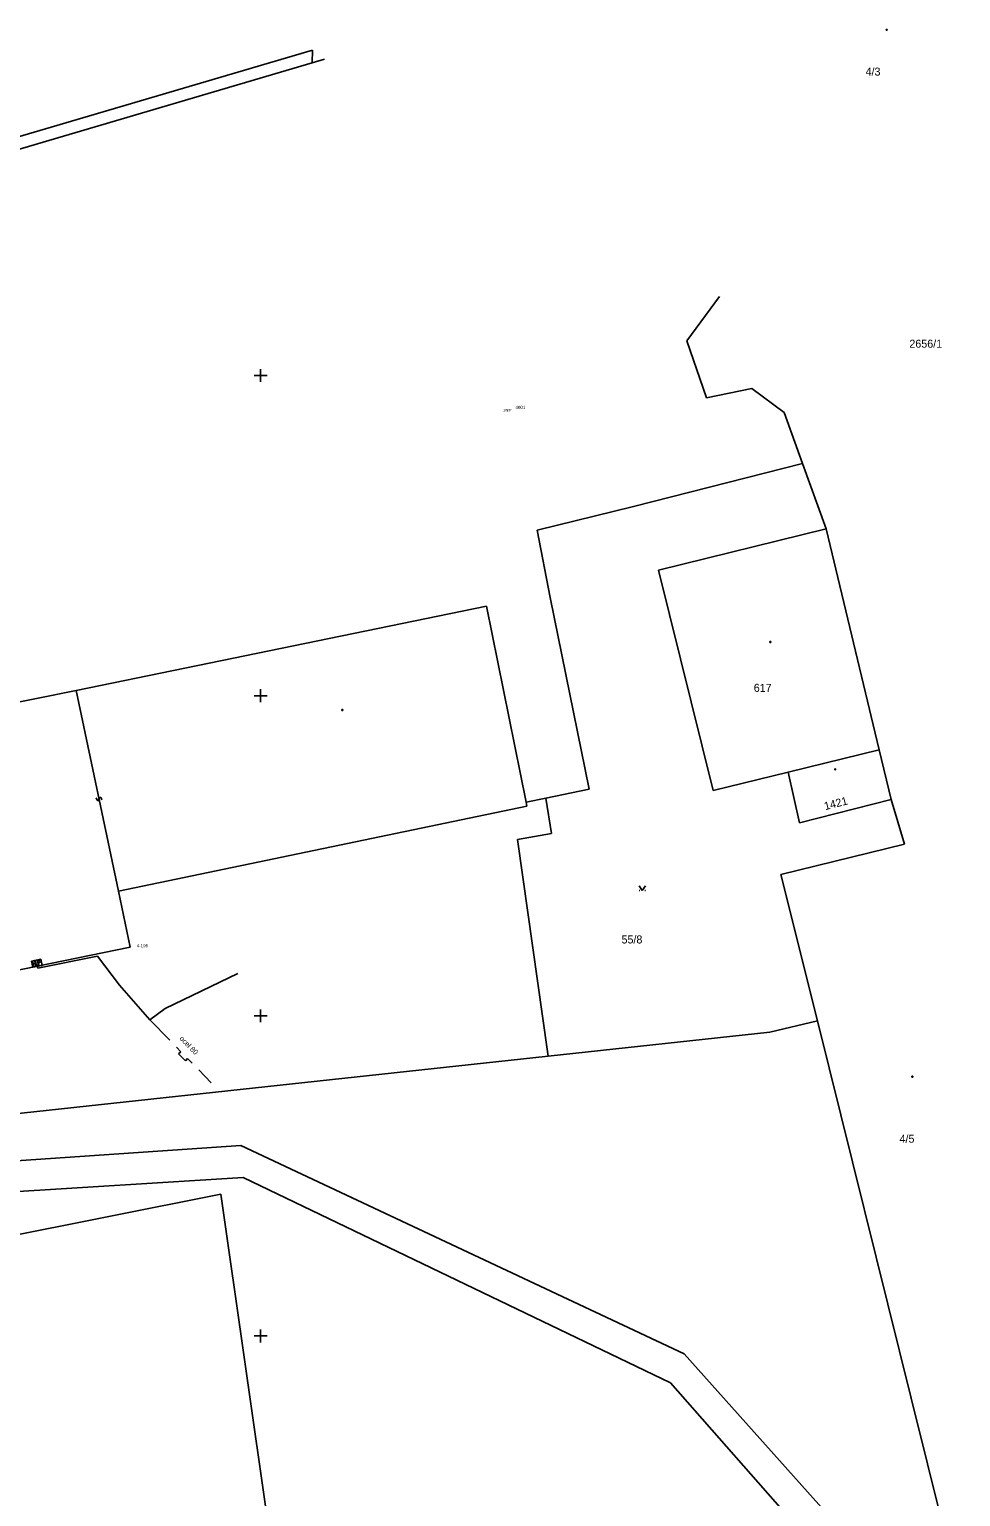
# Model space of a CAD drawing. Extents: x -651478 to -651308, y -994378 to -994071.
# Drawn here: x -651374.4 to -651316.3, y -994310 to -994218.4 of the extents above; entities that cross this region are included whole.
import ezdxf

# ---------------------------------------------------------------- set-up
doc = ezdxf.new("R2010")
doc.units = 0
for name, color, linetype in [('18_TECKY_BODU', 7, 'Continuous'), ('19_CISLA_BODU', 7, 'Continuous'), ('20_REDUKOVANE_VYSKY_BODU', 7, 'Continuous'), ('36_PLYN-VEDENI', 7, 'Continuous'), ('37_PLYN-OBEKTY', 7, 'Continuous'), ('61_UPLNE_VYSKY_BODU', 7, 'Continuous'), ('_KM', 7, 'Continuous'), ('ROZP', 7, 'Continuous'), ('rybnik oprava', 7, 'Continuous')]:
    doc.layers.add(name, color=color, linetype=linetype)

# ---------------------------------------------------------------- blocks, each defined once
blk = doc.blocks.new('POINT_DISPLAY')
blk.add_line((0, 0), (0, 0))
blk = doc.blocks.new('Z402')
for p, q in [((-0.02, 0.02), (0.04, 0.02)), ((-0.02, -0.04), (-0.02, 0.02)), ((0.04, 0.02), (0.04, -0.04)), ((0.04, -0.04), (-0.02, -0.04))]:
    blk.add_line(p, q)
blk = doc.blocks.new('Z3140')
for p, q in [((-0.2, 0.3), (0, 0)), ((-0.2, 0), (-0.16, 0)), ((0, 0), (0.2, 0.3)), ((0.16, 0), (0.2, 0))]:
    blk.add_line(p, q)
blk = doc.blocks.new('Z218')
for p, q in [((-0.04, 0.14), (-0.08, 0.1)), ((-0.08, 0.1), (-0.08, 0.06)), ((-0.08, 0.06), (-0.04, 0.02)), ((0.1, 0.16), (-0.04, 0.14)), ((-0.04, 0.02), (0.04, -0.02)), ((0.04, -0.14), (-0.1, -0.16)), ((0.04, -0.02), (0.08, -0.06)), ((0.08, -0.1), (0.04, -0.14)), ((0.08, -0.06), (0.08, -0.1))]:
    blk.add_line(p, q)
blk = doc.blocks.new('Z70')
for p, q in [((-0.4, 0), (0.4, 0)), ((0, -0.4), (0, 0.4))]:
    blk.add_line(p, q)
blk = doc.blocks.new('Z632')
for p, q in [((-0.7, 0), (-0.3, 0)), ((-0.3, 0), (-0.3, -0.2)), ((0.3, -0.2), (0.3, 0)), ((0.3, 0), (0.7, 0)), ((-0.3, -0.2), (0.3, -0.2))]:
    blk.add_line(p, q)
blk = doc.blocks.new('Z56')
for p, q in [((-0.3, 0), (-0.3, 0.4)), ((-0.3, 0.4), (0.3, 0.4)), ((0.3, 0), (-0.3, 0)), ((-0.22, 0.34), (-0.22, 0.06)), ((-0.22, 0.2), (-0.1, 0.2)), ((-0.1, 0.06), (-0.1, 0.34)), ((-0.06, 0.34), (-0.06, 0.12)), ((-0.06, 0.12), (-0.04, 0.08)), ((-0.04, 0.08), (-0.02, 0.06)), ((-0.02, 0.06), (0.02, 0.06)), ((0.02, 0.06), (0.04, 0.08)), ((0.04, 0.08), (0.06, 0.12)), ((0.06, 0.12), (0.06, 0.34)), ((0.1, 0.06), (0.1, 0.34)), ((0.1, 0.34), (0.18, 0.34)), ((0.18, 0.2), (0.1, 0.2)), ((0.18, 0.34), (0.22, 0.3)), ((0.22, 0.24), (0.18, 0.2)), ((0.22, 0.3), (0.22, 0.24)), ((0.3, 0.4), (0.3, 0))]:
    blk.add_line(p, q)

msp = doc.modelspace()

# ---------------------------------------------------------------- linework, layer by layer
at = {"layer": '36_PLYN-VEDENI'}
for p, q in [((-651373.924, -994277.023), (-651370.198, -994276.275)), ((-651368.81, -994278.08), (-651370.198, -994276.275)), ((-651373.94, -994276.91), (-651373.924, -994277.023)), ((-651361.42, -994277.35), (-651365.97, -994279.55)), ((-651366.93, -994280.25), (-651368.81, -994278.08)), ((-651365.97, -994279.55), (-651366.93, -994280.25)), ((-651366.93, -994280.25), (-651365.679, -994281.527)), ((-651363.859, -994283.384), (-651363.08, -994284.18))]:
    msp.add_line(p, q, dxfattribs=at)
at = {"layer": '_KM'}
for p, q in [((-651382.1, -994227.92), (-651356.79, -994220.47)), ((-651382.09, -994227.14), (-651356.75, -994219.68)), ((-651356.79, -994220.47), (-651356.75, -994219.68)), ((-651356.79, -994220.47), (-651356.01, -994220.24)), ((-651333.37, -994237.84), (-651331.33, -994235.07)), ((-651333.37, -994237.84), (-651332.14, -994241.4)), ((-651332.14, -994241.4), (-651329.31, -994240.81)), ((-651329.31, -994240.81), (-651327.29, -994242.31)), ((-651326.15, -994245.5), (-651327.29, -994242.31)), ((-651326.15, -994245.5), (-651336.7, -994248.19)), ((-651326.15, -994245.5), (-651324.68, -994249.58)), ((-651336.7, -994248.19), (-651342.72, -994249.66)), ((-651342.72, -994249.66), (-651341.92, -994253.87)), ((-651335.14, -994252.15), (-651324.68, -994249.58)), ((-651324.68, -994249.58), (-651321.37, -994263.38)), ((-651335.14, -994252.15), (-651331.73, -994265.92)), ((-651345.88, -994254.41), (-651371.52, -994259.68)), ((-651343.42, -994266.65), (-651345.88, -994254.41)), ((-651341.92, -994253.87), (-651339.48, -994265.85)), ((-651371.52, -994259.68), (-651384.86, -994262.37)), ((-651371.52, -994259.68), (-651368.87, -994272.22)), ((-651327.05, -994264.77), (-651321.37, -994263.38)), ((-651321.37, -994263.38), (-651320.62, -994266.49)), ((-651331.73, -994265.92), (-651327.05, -994264.77)), ((-651327.05, -994264.77), (-651326.34, -994267.94)), ((-651342.19, -994266.4), (-651339.48, -994265.85)), ((-651368.87, -994272.22), (-651343.37, -994266.9)), ((-651342.19, -994266.4), (-651343.42, -994266.65)), ((-651343.37, -994266.9), (-651343.42, -994266.65)), ((-651342.19, -994266.4), (-651341.83, -994268.62)), ((-651326.34, -994267.94), (-651320.62, -994266.49)), ((-651320.62, -994266.49), (-651319.78, -994269.27)), ((-651341.83, -994268.62), (-651343.95, -994268.98)), ((-651343.95, -994268.98), (-651342.06, -994282.38)), ((-651327.5, -994271.17), (-651319.78, -994269.27)), ((-651325.22, -994280.32), (-651327.5, -994271.17)), ((-651368.14, -994275.72), (-651368.87, -994272.22)), ((-651342.04, -994282.52), (-651328.2, -994281.02)), ((-651328.2, -994281.02), (-651325.22, -994280.32)), ((-651325.22, -994280.32), (-651319.37, -994303.88)), ((-651342.04, -994282.52), (-651388.53, -994287.55)), ((-651342.06, -994282.38), (-651342.04, -994282.52)), ((-651397.46, -994290.57), (-651361.24, -994288.11)), ((-651361.24, -994288.11), (-651333.54, -994301.11)), ((-651396.8, -994292.29), (-651361.1, -994290.11)), ((-651361.1, -994290.11), (-651334.39, -994302.92)), ((-651394.77, -994297.58), (-651362.49, -994291.14)), ((-651362.49, -994291.14), (-651358.27, -994320.65)), ((-651333.54, -994301.11), (-651320.58, -994315.61)), ((-651334.39, -994302.92), (-651322.07, -994316.94)), ((-651319.37, -994303.88), (-651316.27, -994316.35))]:
    msp.add_line(p, q, dxfattribs=at)
at = {"layer": 'rybnik oprava'}
msp.add_line((-651394.16, -994281), (-651368.14, -994275.72), dxfattribs=at)

# ---------------------------------------------------------------- block references
at = {"layer": '18_TECKY_BODU'}
for p in [(-651344.48, -994242.09), (-651368.14, -994275.72)]:
    msp.add_blockref('POINT_DISPLAY', p, dxfattribs=at)
at = {"layer": '36_PLYN-VEDENI', "rotation": -45.58909999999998}
msp.add_blockref('Z632', (-651364.769, -994282.456), dxfattribs=at)
at = {"layer": '37_PLYN-OBEKTY', "rotation": 11.4708}
msp.add_blockref('Z56', (-651373.94, -994276.91), dxfattribs=at)
at = {"layer": '_KM'}
for name, p in [('Z402', (-651320.91, -994218.39)), ('Z402', (-651328.16, -994256.64)), ('Z402', (-651354.91, -994260.89)), ('Z402', (-651324.12, -994264.59)), ('Z3140', (-651336.16, -994272.17)), ('Z402', (-651319.29, -994283.8))]:
    msp.add_blockref(name, p, dxfattribs=at)
at = {"layer": '_KM', "rotation": 101.93240000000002}
msp.add_blockref('Z218', (-651370.089, -994266.45), dxfattribs=at)
at = {"layer": 'ROZP'}
for p in [(-651360, -994240), (-651360, -994260), (-651360, -994280), (-651360, -994300)]:
    msp.add_blockref('Z70', p, dxfattribs=at)

# ---------------------------------------------------------------- texts
at = {"layer": '19_CISLA_BODU'}
for s, p in [('4001', (-651344.08, -994242.09)), ('4-196', (-651367.74, -994275.72))]:
    msp.add_text(s, height=0.2, dxfattribs=at).set_placement(p)
at = {"layer": '20_REDUKOVANE_VYSKY_BODU'}
msp.add_text(' 2 17', height=0.16, dxfattribs=at).set_placement((-651344.888, -994242.25))
at = {"layer": '36_PLYN-VEDENI'}
msp.add_text('ocel 80', height=0.32, rotation=314.4109, dxfattribs=at).set_placement((-651365.095, -994281.447))
at = {"layer": '61_UPLNE_VYSKY_BODU'}
msp.add_text('482 17 ', height=0.1, dxfattribs=at).set_placement((-651344.744, -994242.19))
at = {"layer": '_KM'}
for s, p in [('4/3', (-651322.208, -994221.26)), ('2656/1', (-651319.473, -994238.26)), ('617', (-651329.195, -994259.76)), ('55/8', (-651337.455, -994275.48)), ('4/5', (-651320.088, -994287.93))]:
    msp.add_text(s, height=0.5, dxfattribs=at).set_placement(p)
msp.add_text('1421', height=0.5, rotation=14.382, dxfattribs=at).set_placement((-651324.73, -994267.156))

doc.saveas('drawing.dxf')
